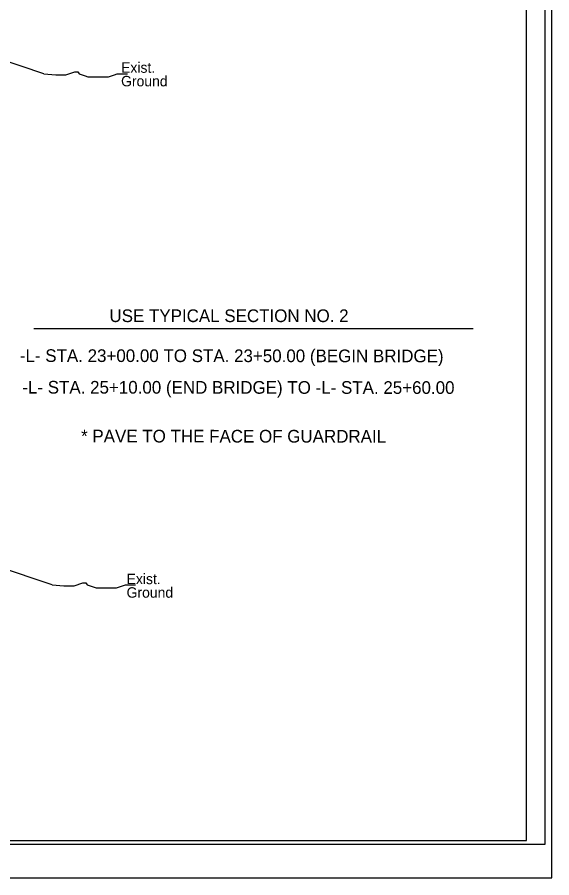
# Model space of a CAD drawing. Extents: x 1497225 to 1499181, y 579958 to 582278.
# Drawn here: x 1498551 to 1498909, y 581178 to 581755 of the extents above; entities that cross this region are included whole.
import ezdxf

# ---------------------------------------------------------------- set-up
doc = ezdxf.new("R2010")
doc.units = 0
for name, color, linetype in [('Old_Level_1', 7, 'Continuous'), ('Sheet Cutting Line CELL', 7, 'Continuous'), ('Sheet Plot Border Inside CELL', 7, 'Continuous'), ('Sheet Plot Border Outside CELL', 7, 'Continuous'), ('Sheet Typical CELL', 7, 'Continuous'), ('Typical Text Label CELL', 7, 'Continuous')]:
    doc.layers.add(name, color=color, linetype=linetype)

msp = doc.modelspace()

# ---------------------------------------------------------------- linework, layer by layer
at = {"layer": 'Old_Level_1'}
for p, q in [((1498568.54, 581717.2), (1498487.76, 581744.13)), ((1498573.97, 581374.48), (1498487.76, 581403.22))]:
    msp.add_line(p, q, dxfattribs=at)
for points in [[(1498568.54, 581717.2), (1498576.41, 581716.55), (1498578.38, 581716.55), (1498581.33, 581716.55), (1498583.3, 581716.55), (1498585.26, 581717.2), (1498587.23, 581717.86), (1498589.2, 581718.52), (1498591.16, 581718.52), (1498592.15, 581717.2), (1498594.12, 581716.55), (1498596.08, 581715.89), (1498598.05, 581715.24), (1498600.02, 581715.24), (1498601.98, 581715.24), (1498603.95, 581715.24), (1498605.92, 581715.24), (1498607.88, 581715.24), (1498609.85, 581715.24), (1498611.82, 581715.24), (1498613.78, 581715.89), (1498615.75, 581716.55), (1498617.72, 581717.2), (1498620.67, 581717.2), (1498622.64, 581717.2), (1498624.61, 581717.2)], [(1498573.97, 581374.48), (1498581.84, 581373.83), (1498583.8, 581373.83), (1498586.76, 581373.83), (1498588.72, 581373.83), (1498590.69, 581374.48), (1498592.66, 581375.14), (1498594.62, 581375.79), (1498596.59, 581375.79), (1498597.58, 581374.48), (1498599.54, 581373.83), (1498601.51, 581373.17), (1498603.48, 581372.51), (1498605.45, 581372.51), (1498607.41, 581372.51), (1498609.38, 581372.51), (1498611.35, 581372.51), (1498613.31, 581372.51), (1498615.28, 581372.51), (1498617.25, 581372.51), (1498619.21, 581373.17), (1498621.18, 581373.83), (1498623.15, 581374.48), (1498626.1, 581374.48), (1498628.07, 581374.48), (1498630.03, 581374.48)]]:
    msp.add_lwpolyline(points, dxfattribs=at)
at = {"layer": 'Sheet Cutting Line CELL'}
msp.add_line((1497225.23, 581177.96), (1498909.23, 581177.96), dxfattribs=at)
at = {"layer": 'Sheet Plot Border Inside CELL'}
msp.add_lwpolyline([(1498904.73, 582255.51), (1497238.23, 582255.51), (1497238.23, 581200.41), (1498904.73, 581200.41)], close=True, dxfattribs=at)
at = {"layer": 'Sheet Plot Border Outside CELL'}
msp.add_lwpolyline([(1498909.23, 582277.96), (1497225.23, 582277.96), (1497225.23, 581177.96), (1498909.23, 581177.96)], close=True, dxfattribs=at)
at = {"layer": 'Sheet Typical CELL'}
msp.add_lwpolyline([(1498892.23, 582252.96), (1497392.23, 582252.96), (1497392.23, 581202.96), (1498892.23, 581202.96)], close=True, dxfattribs=at)
at = {"layer": 'Typical Text Label CELL'}
msp.add_line((1498561.77, 581546.37), (1498856.46, 581546.37), dxfattribs=at)

# ---------------------------------------------------------------- texts
at = {"layer": 'Old_Level_1'}
for s, height, p in [('Exist.', 7, (1498620.26, 581717.87)), ('Ground', 7, (1498620.25, 581708.77)), ('-L- STA. 23+00.00 TO STA. 23+50.00 (BEGIN BRIDGE)', 8.5, (1498552.34, 581523.94)), ('-L- STA. 25+10.00 (END BRIDGE) TO -L- STA. 25+60.00', 8.5, (1498554, 581502.73)), ('* PAVE TO THE FACE OF GUARDRAIL', 8.5, (1498593.43, 581469.97)), ('Exist.', 7, (1498623.96, 581374.91)), ('Ground', 7, (1498623.95, 581365.81))]:
    msp.add_text(s, height=height, rotation=359.94924, dxfattribs=at).set_placement(p)
at = {"layer": 'Typical Text Label CELL'}
msp.add_text('USE TYPICAL SECTION NO. 2', height=8.5, dxfattribs=at).set_placement((1498612.46, 581550.66))

doc.saveas('drawing.dxf')
